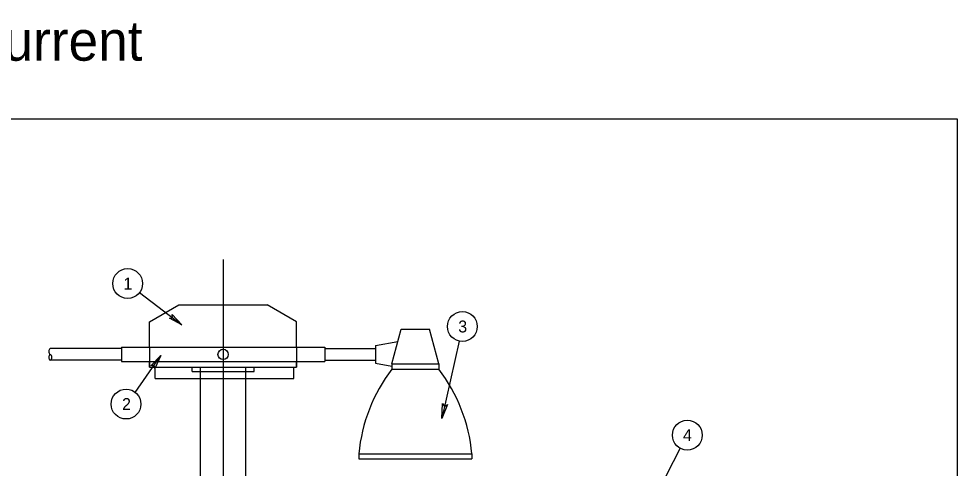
# Model space of a CAD drawing. Extents: x 99968 to 128667, y 90163 to 102182.
# Drawn here: x 102224 to 103167, y 92116 to 92567 of the extents above; entities that cross this region are included whole.
import ezdxf

# ---------------------------------------------------------------- set-up
doc = ezdxf.new("R2010")
doc.units = 0
for name, color, linetype in [('Default', 7, 'Continuous'), ('Level 7', 7, 'Continuous'), ('RD Standard Plans Active', 7, 'Continuous')]:
    doc.layers.add(name, color=color, linetype=linetype)

msp = doc.modelspace()

# ---------------------------------------------------------------- linework, layer by layer
at = {"layer": 'Default'}
msp.add_lwpolyline([(99967.52, 92466.53), (103167.2, 92466.53), (103167.2, 90266.93), (99967.52, 90266.93)], close=True, dxfattribs=at)
at = {"layer": 'RD Standard Plans Active'}
for p, q in [((102429.49, 92325.22), (102429.49, 91653.75)), ((102345.55, 92291.98), (102388.16, 92259.51)), ((102355.71, 92262.56), (102385.16, 92279.58)), ((102385.16, 92279.58), (102473.82, 92279.58)), ((102503.28, 92262.56), (102473.82, 92279.58)), ((102355.71, 92237.01), (102355.71, 92262.56)), ((102503.28, 92237.01), (102503.28, 92262.56)), ((102599.09, 92220.33), (102608.51, 92255.35)), ((102608.51, 92255.35), (102636.89, 92255.35)), ((102646.32, 92220.33), (102636.89, 92255.35)), ((102327.33, 92235.88), (102255.7, 92235.88)), ((102327.33, 92237.01), (102531.66, 92237.01)), ((102327.33, 92237.01), (102327.33, 92222.82)), ((102355.71, 92237.01), (102355.71, 92217.15)), ((102503.28, 92237.01), (102503.28, 92217.15)), ((102531.66, 92237.01), (102531.66, 92222.82)), ((102531.66, 92235.88), (102582.75, 92235.88)), ((102582.75, 92238.72), (102605.11, 92242.69)), ((102582.75, 92238.72), (102582.75, 92221.12)), ((102666.65, 92243.27), (102649.17, 92165.42)), ((102341.3, 92191.73), (102367.05, 92228.79)), ((102327.33, 92223.96), (102255.7, 92223.96)), ((102327.33, 92222.82), (102531.66, 92222.82)), ((102355.71, 92217.15), (102355.71, 92222.82)), ((102355.71, 92217.15), (102503.28, 92217.15)), ((102361.38, 92205.8), (102361.38, 92217.15)), ((102398.28, 92212.61), (102398.28, 92217.15)), ((102406.79, 91722.88), (102406.79, 92217.15)), ((102452.2, 91722.88), (102452.2, 92217.15)), ((102460.71, 92212.61), (102460.71, 92217.15)), ((102500.44, 92205.8), (102500.44, 92217.15)), ((102503.28, 92217.15), (102503.28, 92222.82)), ((102531.66, 92223.96), (102582.75, 92223.96)), ((102582.75, 92221.12), (102599.09, 92218.23)), ((102599.09, 92220.33), (102646.32, 92220.33)), ((102599.09, 92220.33), (102599.09, 92215.16)), ((102646.32, 92220.33), (102646.32, 92215.16)), ((102398.28, 92212.61), (102460.71, 92212.61)), ((102599.09, 92215.16), (102646.32, 92215.16)), ((102361.38, 92205.8), (102500.44, 92205.8)), ((102888.91, 92135.54), (102851.76, 92063.61)), ((102565.94, 92130.02), (102679.46, 92130.02)), ((102565.94, 92130.02), (102565.94, 92124.86)), ((102565.94, 92124.86), (102679.46, 92124.86)), ((102679.46, 92130.02), (102679.46, 92124.86))]:
    msp.add_line(p, q, dxfattribs=at)
for points in [[(102378.39, 92269.96), (102388.16, 92259.51), (102375.49, 92266.15), (102378.71, 92266.71)], [(102357.04, 92218.57), (102367.05, 92228.79), (102360.97, 92215.84), (102360.27, 92219.03)], [(102654.9, 92179.41), (102649.17, 92165.42), (102649.97, 92180.52), (102651.92, 92177.68)]]:
    msp.add_lwpolyline(points, close=True, dxfattribs=at)
for centre, radius in [((102333.62, 92301.07), 15), ((102669.93, 92257.91), 15), ((102429.49, 92229.92), 5.16), ((102331.97, 92179.99), 15), ((102895.99, 92148.76), 15)]:
    msp.add_circle(centre, radius, dxfattribs=at)
for centre, radius, start, end in [((102258.24, 92232.9), 3.92, 130.46997, 229.53003), ((102258.24, 92226.94), 3.92, 130.46997, 229.53003), ((102254.2, 92226.94), 3.34, 296.70131, 63.29869), ((102730.22, 92115.09), 164.95, 142.64968, 174.80508), ((102515.19, 92115.09), 164.95, 5.19492, 37.35033)]:
    msp.add_arc(centre, radius, start, end, dxfattribs=at)

# ---------------------------------------------------------------- texts
at = {"layer": 'Level 7'}
msp.add_text('Effective Letting Date current', height=39.9999, dxfattribs=at).set_placement((101658.81, 92525.04))
at = {"layer": 'RD Standard Plans Active'}
for s, p in [('1', (102329.41, 92295.07)), ('3', (102665.8, 92251.91)), ('2', (102328, 92173.99)), ('4', (102891.66, 92142.76))]:
    msp.add_text(s, height=12, dxfattribs=at).set_placement(p)

doc.saveas('drawing.dxf')
